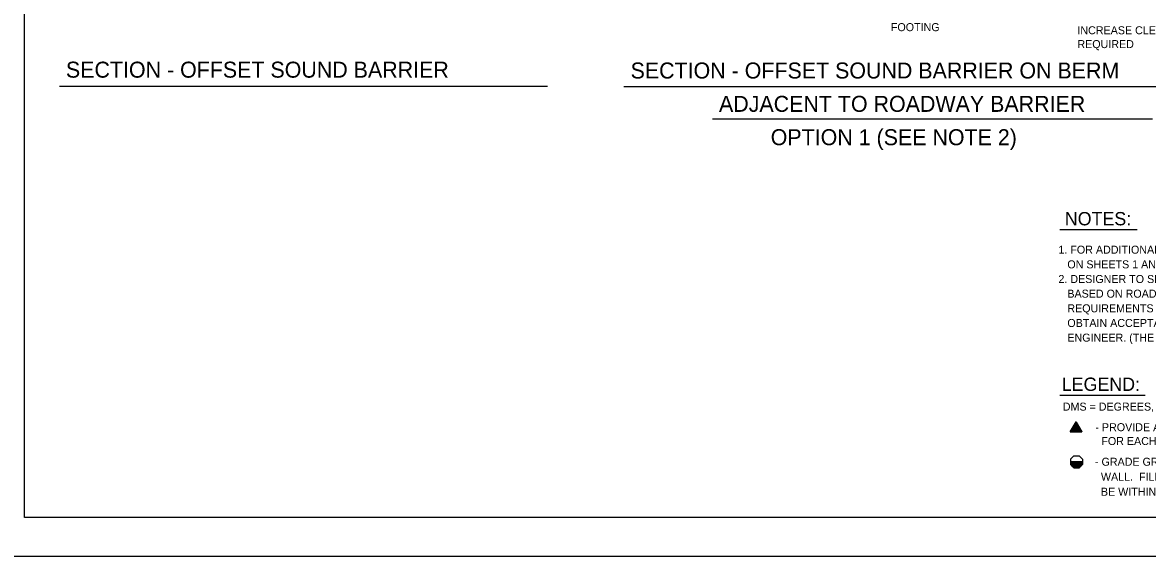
# Model space of a CAD drawing. Extents: x 3385 to 6532, y -616 to 1166.
# Drawn here: x 3800.6 to 4232.5, y -22.3 to 182.8 of the extents above; entities that cross this region are included whole.
import ezdxf

# ---------------------------------------------------------------- set-up
doc = ezdxf.new("R2010")
doc.units = 0
for name, color, linetype in [('1', 7, 'Continuous'), ('2', 7, 'Continuous'), ('PLT-BNDY', 7, 'Continuous')]:
    doc.layers.add(name, color=color, linetype=linetype)

msp = doc.modelspace()

# ---------------------------------------------------------------- linework, layer by layer
at = {"layer": '1'}
for p, q in [((3814.77, 158.4), (4002.18, 158.4)), ((4031.47, 158.27), (4269.37, 158.27)), ((4065.45, 145.88), (4234.4, 145.88)), ((4198.75, 103.28), (4228.45, 103.28)), ((4198.75, 39.69), (4231.54, 39.69)), ((4205.07, 26.83), (4205.07, 26.83)), ((4202.89, 14.18), (4207.5, 14.18)), ((4202.89, 13.38), (4207.5, 13.38)), ((4202.89, 13.28), (4207.5, 13.28)), ((4202.89, 13.18), (4207.5, 13.18)), ((4202.89, 13.08), (4207.5, 13.08)), ((4204.15, 16.37), (4202.9, 15.12)), ((4202.9, 15.12), (4202.9, 13)), ((4202.9, 13.88), (4207.5, 13.88)), ((4202.9, 13.78), (4207.5, 13.78)), ((4202.9, 13.68), (4207.5, 13.68)), ((4202.9, 13.58), (4207.5, 13.58)), ((4202.9, 13.48), (4207.5, 13.48)), ((4204.15, 11.75), (4202.9, 13)), ((4202.91, 14.08), (4207.5, 14.08)), ((4202.91, 13.98), (4207.5, 13.98)), ((4202.91, 12.98), (4207.46, 12.98)), ((4204.15, 16.37), (4206.27, 16.37)), ((4205.99, 14.18), (4207.5, 14.18)), ((4206.27, 16.37), (4207.52, 15.12)), ((4206.27, 11.75), (4207.52, 13)), ((4207.52, 15.12), (4207.52, 13)), ((4203.01, 12.88), (4207.37, 12.88)), ((4203.11, 12.78), (4207.27, 12.78)), ((4203.21, 12.68), (4207.17, 12.68)), ((4203.31, 12.58), (4207.08, 12.58)), ((4203.42, 12.48), (4206.98, 12.48)), ((4203.52, 12.38), (4206.89, 12.38)), ((4203.62, 12.28), (4206.79, 12.28)), ((4203.72, 12.18), (4206.69, 12.18)), ((4203.82, 12.08), (4206.6, 12.08)), ((4203.93, 11.98), (4206.5, 11.98)), ((4204.03, 11.88), (4206.4, 11.88)), ((4204.13, 11.78), (4206.31, 11.78)), ((4204.15, 11.75), (4206.27, 11.75))]:
    msp.add_line(p, q, dxfattribs=at)
for points in [[(4202.83, 25.54), (4207.3, 25.54), (4205.07, 29.41), (4202.83, 25.54)], [(4202.83, 25.54), (4205.07, 29.41), (4207.3, 25.54), (4202.83, 25.54), (4205.06, 29.29), (4207.23, 25.6), (4202.92, 25.59), (4205.07, 29.18), (4207.13, 25.65), (4203.03, 25.64), (4205.07, 29.06), (4207.03, 25.72), (4203.12, 25.69), (4205.07, 28.95), (4206.94, 25.77), (4203.23, 25.76), (4205.07, 28.81), (4206.83, 25.83), (4203.35, 25.83), (4205.07, 28.67), (4206.72, 25.89), (4203.45, 25.89), (4205.06, 28.54), (4206.61, 25.96), (4203.56, 25.95), (4205.06, 28.41), (4206.49, 26.03), (4203.67, 26.01), (4205.08, 28.29), (4206.36, 26.09), (4203.78, 26.08), (4205.08, 28.16), (4206.22, 26.18), (4203.9, 26.14), (4205.08, 28.01), (4206.11, 26.26), (4204.02, 26.2), (4205.07, 27.88), (4205.99, 26.33), (4204.15, 26.27), (4205.08, 27.75), (4205.88, 26.39), (4204.28, 26.33), (4205.07, 27.6), (4205.75, 26.46), (4204.42, 26.4), (4205.07, 27.47), (4205.61, 26.53), (4204.53, 26.47), (4205.07, 27.34), (4205.49, 26.6), (4204.65, 26.53), (4205.07, 27.22), (4205.38, 26.65), (4204.76, 26.59), (4205.07, 27.09), (4205.29, 26.71), (4204.86, 26.64), (4205.07, 26.97), (4205.2, 26.75), (4204.98, 26.72), (4205.07, 26.83), (4207.29, 25.56), (4205.07, 26.83), (4205.07, 29.38), (4205.07, 26.82), (4202.84, 25.55)]]:
    msp.add_lwpolyline(points, dxfattribs=at)
at = {"layer": '2'}
for p, q in [((3801.34, -7.31), (3801.34, 556.69)), ((4587.34, -7.31), (3801.34, -7.31))]:
    msp.add_line(p, q, dxfattribs=at)
at = {"layer": 'PLT-BNDY'}
msp.add_lwpolyline([(3761.34, 571.69), (4602.34, 571.69), (4602.34, -22.31), (3761.34, -22.31)], close=True, dxfattribs=at)

# ---------------------------------------------------------------- texts
at = {"layer": '1'}
for s, height, p in [('FOOTING', 3.072, (4133.95, 179.51)), ('INCREASE CLEARANCES AS', 3.0721, (4205.55, 178.31)), ('REQUIRED', 3.072, (4205.55, 173)), ('SECTION - OFFSET SOUND BARRIER', 6.144, (3817.27, 161.64)), ('SECTION - OFFSET SOUND BARRIER ON BERM', 6.144, (4034.02, 161.32)), ('ADJACENT TO ROADWAY BARRIER', 6.144, (4067.96, 148.51)), ('OPTION 1 (SEE NOTE 2)', 6.144, (4087.82, 135.7)), ('NOTES:', 5.117, (4200.72, 104.91)), ('1. FOR ADDITIONAL INFORMATION REFER TO NOTES', 3.072, (4198.27, 94.03)), ('   ON SHEETS 1 AND 2.', 3.072, (4198.27, 88.39)), ('2. DESIGNER TO SELECT WHICH OPTION IS USED', 3.072, (4198.27, 82.76)), ('   BASED ON ROADWAY GEOMETRICS, RIGHT-OF-WAY', 3.072, (4198.27, 77.13)), ('   REQUIREMENTS AND ALL OTHER CONSTRAINTS.', 3.072, (4198.27, 71.5)), ('   OBTAIN ACCEPTANCE FROM THE DISTRICT BRIDGE', 3.072, (4198.27, 65.87)), ('   ENGINEER. (THE DEPARTMENT PREFERS OPTION 1)', 3.072, (4198.27, 60.24)), ('LEGEND:', 5.117, (4199.54, 41.31)), ('DMS = DEGREES, MINUTES, AND SECONDS', 3.072, (4199.94, 33.74)), ('- PROVIDE A MINIMUM OF TWO CABLE CONNECTIONS', 3.0721, (4212.46, 25.83)), ('  FOR EACH PANEL-TO-PANEL CONNECTION.', 3.0721, (4212.46, 20.52)), ('- GRADE GROUND TO DRAIN WATER AWAY FROM THE', 3.072, (4212.3, 12.56)), ('  WALL.  FILL DEPTH ON EACH SIDE OF WALL TO', 3.072, (4212.3, 6.8)), ('  BE WITHIN 1\'-0" DIFFERANCE.', 3.072, (4212.3, 1.04))]:
    msp.add_text(s, height=height, dxfattribs=at).set_placement(p)

doc.saveas('drawing.dxf')
